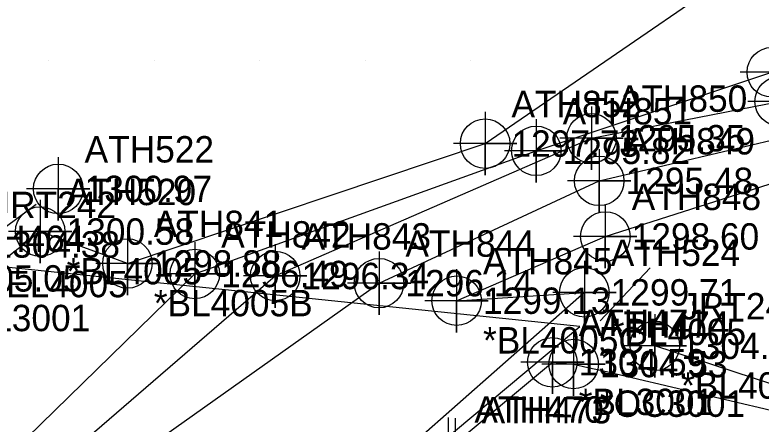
# Model space of a CAD drawing. Extents: x 1234484 to 1235382, y 695050 to 695510.
# Drawn here: x 1234936.8 to 1235007.5, y 695315.6 to 695354.3 of the extents above; entities that cross this region are included whole.
import ezdxf

# ---------------------------------------------------------------- set-up
doc = ezdxf.new("R2010")
doc.units = 0
for name, color, linetype in [('Exist DTM Breakline', 7, 'Continuous'), ('Exist DTM Breakline Cogo Comment', 7, 'Continuous'), ('Exist DTM Breakline Cogo Elevation', 7, 'Continuous'), ('Exist DTM Breakline Cogo Number', 7, 'Continuous'), ('Exist DTM Breakline Cogo Point CELL', 7, 'Continuous'), ('Exist DTM Breakline Underwater', 7, 'Continuous'), ('Exist DTM Crownline Cogo Number', 7, 'Continuous'), ('Exist DTM Crownline Cogo Point CELL', 7, 'Continuous'), ('Exist DTM Drainline Cogo Elevation', 7, 'Continuous'), ('Exist DTM Drainline Cogo Number', 7, 'Continuous'), ('Exist DTM Drainline Cogo Point CELL', 7, 'Continuous'), ('Exist DTM QL2 LIDAR Elevation Point', 7, 'Continuous'), ('Exist DTM Regular Point CELL', 7, 'Continuous'), ('Exist DTM Regular Point Cogo Elevation', 7, 'Continuous'), ('Exist DTM Regular Point Cogo Number', 7, 'Continuous'), ('Exist DTM Regular Point Underwater CELL', 7, 'Continuous'), ('Exist DTM Regular Point Underwater Cogo Elevation', 7, 'Continuous'), ('Exist DTM Regular Point Underwater Cogo Number', 7, 'Continuous'), ('Exist Hydro Stream or Body of Water', 7, 'Continuous'), ('Exist Roads EOP', 7, 'Continuous'), ('Exist Roads EOP Cogo Comment', 7, 'Continuous'), ('Exist Roads EOP Cogo Elevation', 7, 'Continuous'), ('Exist Roads EOP Cogo Number', 7, 'Continuous'), ('Exist Roads EOP Cogo Point CELL', 7, 'Continuous'), ('Exist Structure Major Deck Tunnel Box Culvert', 7, 'Continuous')]:
    doc.layers.add(name, color=color, linetype=linetype)

msp = doc.modelspace()

# ---------------------------------------------------------------- linework, layer by layer
at = {"layer": 'Exist DTM Breakline'}
for p, q in [((1234932.724, 695331.913), (1234938.803, 695336.41)), ((1234939.196, 695333.825), (1234905.457, 695307.608)), ((1234947.461, 695330.8), (1234939.196, 695333.825)), ((1234992.275, 695325.377), (1234997.012, 695330.381)), ((1234990.761, 695328.067), (1234961.429, 695302.218)), ((1234978.66, 695327.276), (1234990.761, 695328.067))]:
    msp.add_line(p, q, dxfattribs=at)
for points in [[(1234947.461, 695330.8), (1234981.356, 695342.155), (1235004.028, 695357.73), (1235022.786, 695369.361), (1235002.521, 695380.756), (1235001.421, 695384.893), (1235033.023, 695378.856), (1235065.819, 695386.67), (1235084.63, 695404.567)], [(1234978.66, 695327.276), (1234992.748, 695333.364), (1235012.047, 695339.528), (1235045.835, 695358.491), (1235079.523, 695374.606), (1235097.5, 695391.337)], [(1235319.256, 695177.55), (1235278.534, 695201.47), (1235237.781, 695224.217), (1235188.481, 695250.698), (1235134.96, 695275.849), (1235082.338, 695295.901), (1235034.938, 695310.723), (1234997.435, 695322.999)]]:
    msp.add_lwpolyline(points, dxfattribs=at)
at = {"layer": 'Exist DTM Breakline Cogo Point CELL'}
for points in [[(1234981.356, 695345.155), (1234981.356, 695339.155), (1234981.356, 695342.155), (1234984.356, 695342.155), (1234978.356, 695342.155)], [(1234939.196, 695336.825), (1234939.196, 695330.825), (1234939.196, 695333.825), (1234942.196, 695333.825), (1234936.196, 695333.825)], [(1234992.748, 695336.364), (1234992.748, 695330.364), (1234992.748, 695333.364), (1234995.748, 695333.364), (1234989.748, 695333.364)], [(1234947.461, 695333.8), (1234947.461, 695327.8), (1234947.461, 695330.8), (1234950.461, 695330.8), (1234944.461, 695330.8)], [(1234990.761, 695331.067), (1234990.761, 695325.067), (1234990.761, 695328.067), (1234993.761, 695328.067), (1234987.761, 695328.067)], [(1234978.66, 695330.276), (1234978.66, 695324.276), (1234978.66, 695327.276), (1234981.66, 695327.276), (1234975.66, 695327.276)], [(1234997.435, 695325.999), (1234997.435, 695319.999), (1234997.435, 695322.999), (1235000.435, 695322.999), (1234994.435, 695322.999)]]:
    msp.add_lwpolyline(points, dxfattribs=at)
for centre in [(1234981.356, 695342.155), (1234939.196, 695333.825), (1234992.748, 695333.364), (1234947.461, 695330.8), (1234990.761, 695328.067), (1234978.66, 695327.276), (1234997.435, 695322.999)]:
    msp.add_circle(centre, 2.344, dxfattribs=at)
at = {"layer": 'Exist DTM Breakline Underwater'}
msp.add_lwpolyline([(1234766.421, 695209.389), (1234812.885, 695247.237), (1234843.411, 695272.621), (1234869.986, 695279.055), (1234895.378, 695289.036), (1234916.238, 695295.408), (1234934.131, 695306.081), (1234961.466, 695329.617), (1234991.436, 695342.664), (1235009.265, 695346.147), (1235040.352, 695365.623), (1235072.367, 695380.008), (1235092.174, 695396.335)], dxfattribs=at)
at = {"layer": 'Exist DTM Crownline Cogo Point CELL'}
for points in [[(1234977.842, 695316.219), (1234977.842, 695310.219), (1234977.842, 695313.219), (1234980.842, 695313.219), (1234974.842, 695313.219)], [(1234978.534, 695316.159), (1234978.534, 695310.159), (1234978.534, 695313.159), (1234981.534, 695313.159), (1234975.534, 695313.159)]]:
    msp.add_lwpolyline(points, dxfattribs=at)
at = {"layer": 'Exist DTM Drainline Cogo Point CELL'}
for points in [[(1235008.526, 695351.915), (1235008.526, 695345.915), (1235008.526, 695348.915), (1235011.526, 695348.915), (1235005.526, 695348.915)], [(1234986.204, 695344.472), (1234986.204, 695338.472), (1234986.204, 695341.472), (1234989.204, 695341.472), (1234983.204, 695341.472)], [(1234992.169, 695341.626), (1234992.169, 695335.626), (1234992.169, 695338.626), (1234995.169, 695338.626), (1234989.169, 695338.626)], [(1234953.845, 695332.807), (1234953.845, 695326.807), (1234953.845, 695329.807), (1234956.845, 695329.807), (1234950.845, 695329.807)], [(1234971.304, 695331.94), (1234971.304, 695325.94), (1234971.304, 695328.94), (1234974.304, 695328.94), (1234968.304, 695328.94)]]:
    msp.add_lwpolyline(points, dxfattribs=at)
for centre in [(1235008.526, 695348.915), (1234986.204, 695341.472), (1234992.169, 695338.626), (1234953.845, 695329.807), (1234971.304, 695328.94)]:
    msp.add_circle(centre, 2.344, dxfattribs=at)
at = {"layer": 'Exist DTM QL2 LIDAR Elevation Point'}
for p, q in [((1234940, 695350), (1234940, 695350)), ((1234950, 695350), (1234950, 695350)), ((1234960, 695350), (1234960, 695350)), ((1234970, 695350), (1234970, 695350)), ((1234980, 695350), (1234980, 695350)), ((1234940, 695340), (1234940, 695340))]:
    msp.add_line(p, q, dxfattribs=at)
at = {"layer": 'Exist DTM Regular Point CELL'}
msp.add_lwpolyline([(1234940.904, 695340.865), (1234940.904, 695334.865), (1234940.904, 695337.865), (1234943.904, 695337.865), (1234937.904, 695337.865)], dxfattribs=at)
msp.add_circle((1234940.904, 695337.865), 2.344, dxfattribs=at)
at = {"layer": 'Exist DTM Regular Point Underwater CELL'}
for points in [[(1235009.265, 695349.147), (1235009.265, 695343.147), (1235009.265, 695346.147), (1235012.265, 695346.147), (1235006.265, 695346.147)], [(1234991.436, 695345.664), (1234991.436, 695339.664), (1234991.436, 695342.664), (1234994.436, 695342.664), (1234988.436, 695342.664)], [(1234961.466, 695332.617), (1234961.466, 695326.617), (1234961.466, 695329.617), (1234964.466, 695329.617), (1234958.466, 695329.617)]]:
    msp.add_lwpolyline(points, dxfattribs=at)
for centre in [(1235009.265, 695346.147), (1234991.436, 695342.664), (1234961.466, 695329.617)]:
    msp.add_circle(centre, 2.344, dxfattribs=at)
at = {"layer": 'Exist Hydro Stream or Body of Water'}
for points in [[(1234766.439, 695214.543), (1234809.451, 695250.146), (1234840.783, 695273.683), (1234870.231, 695281.467), (1234894.384, 695292.767), (1234915.014, 695298.345), (1234929.933, 695306.511), (1234953.845, 695329.807), (1234986.204, 695341.472), (1235008.526, 695348.915), (1235037.336, 695368.653), (1235069.491, 695383.302), (1235088.448, 695400.861)], [(1234938.044, 695305.366), (1234971.304, 695328.94), (1234992.169, 695338.626), (1235010.649, 695342.979), (1235043.523, 695362.073), (1235076.562, 695377.561), (1235094.01, 695394.044)]]:
    msp.add_lwpolyline(points, dxfattribs=at)
at = {"layer": 'Exist Roads EOP'}
msp.add_line((1234987.73, 695321.443), (1234989.744, 695321.275), dxfattribs=at)
msp.add_lwpolyline([(1234968.075, 695304.88), (1234977.842, 695313.219), (1234987.73, 695321.443)], dxfattribs=at)
msp.add_spline([(1234989.744, 695321.275), (1235032.632, 695310.758), (1235082.97, 695294.625), (1235134.247, 695274.482), (1235183.928, 695250.955), (1235232.115, 695225.68)], degree=3, dxfattribs=at)
at = {"layer": 'Exist Roads EOP Cogo Point CELL'}
for points in [[(1234987.73, 695324.443), (1234987.73, 695318.443), (1234987.73, 695321.443), (1234990.73, 695321.443), (1234984.73, 695321.443)], [(1234989.744, 695324.275), (1234989.744, 695318.275), (1234989.744, 695321.275), (1234992.744, 695321.275), (1234986.744, 695321.275)]]:
    msp.add_lwpolyline(points, dxfattribs=at)
for centre in [(1234987.73, 695321.443), (1234989.744, 695321.275)]:
    msp.add_circle(centre, 2.344, dxfattribs=at)
at = {"layer": 'Exist Structure Major Deck Tunnel Box Culvert'}
msp.add_lwpolyline([(1234932.242, 695330.836), (1234906.381, 695309.848), (1234965.045, 695303.686), (1234990.33, 695324.837), (1234932.242, 695330.836)], dxfattribs=at)

# ---------------------------------------------------------------- texts
at = {"layer": 'Exist DTM Breakline Cogo Comment'}
for s, p in [('*BL4005', (1234941.696, 695328.825)), ('*EL4005', (1234934.671, 695327.602)), ('*BL4005B', (1234949.961, 695325.8)), ('*BL4005', (1234993.261, 695323.067)), ('*BL4005C', (1234981.16, 695322.276)), ('*BL4005', (1234999.935, 695317.999))]:
    msp.add_text(s, height=2.5, dxfattribs=at).set_placement(p)
at = {"layer": 'Exist DTM Breakline Cogo Elevation'}
for s, p in [('1297.73', (1234983.856, 695340.905)), ('1300.58', (1234941.696, 695332.575)), ('1298.60', (1234995.248, 695332.114)), ('1304.38', (1234934.671, 695331.352)), ('1298.88', (1234949.961, 695329.55)), ('1299.71', (1234993.261, 695326.817)), ('1299.13', (1234981.16, 695326.026)), ('1304.20', (1234999.935, 695321.749))]:
    msp.add_text(s, height=2.5, dxfattribs=at).set_placement(p)
at = {"layer": 'Exist DTM Breakline Cogo Number'}
for s, p in [('ATH852', (1234983.856, 695344.655)), ('ATH520', (1234941.696, 695336.325)), ('ATH848', (1234995.248, 695335.864)), ('JRT242', (1234934.671, 695335.102)), ('ATH841', (1234949.961, 695333.3)), ('ATH524', (1234993.261, 695330.567)), ('ATH845', (1234981.16, 695329.776)), ('JRT243', (1234999.935, 695325.499))]:
    msp.add_text(s, height=2.5, dxfattribs=at).set_placement(p)
at = {"layer": 'Exist DTM Crownline Cogo Number'}
for s, p in [('ATH470', (1234980.342, 695315.719)), ('ATH473', (1234981.034, 695315.659))]:
    msp.add_text(s, height=2.5, dxfattribs=at).set_placement(p)
at = {"layer": 'Exist DTM Drainline Cogo Elevation'}
for s, p in [('1295.82', (1234988.704, 695340.222)), ('1295.48', (1234994.669, 695337.376)), ('1296.49', (1234956.345, 695328.557)), ('1296.14', (1234973.804, 695327.69))]:
    msp.add_text(s, height=2.5, dxfattribs=at).set_placement(p)
at = {"layer": 'Exist DTM Drainline Cogo Number'}
for s, p in [('ATH851', (1234988.704, 695343.972)), ('ATH849', (1234994.669, 695341.126)), ('ATH842', (1234956.345, 695332.307)), ('ATH844', (1234973.804, 695331.44))]:
    msp.add_text(s, height=2.5, dxfattribs=at).set_placement(p)
at = {"layer": 'Exist DTM Regular Point Cogo Elevation'}
msp.add_text('1300.97', height=2.5, dxfattribs=at).set_placement((1234943.404, 695336.615))
at = {"layer": 'Exist DTM Regular Point Cogo Number'}
msp.add_text('ATH522', height=2.5, dxfattribs=at).set_placement((1234943.404, 695340.365))
at = {"layer": 'Exist DTM Regular Point Underwater Cogo Elevation'}
for s, p in [('1295.35', (1234993.936, 695341.414)), ('1296.34', (1234963.966, 695328.367))]:
    msp.add_text(s, height=2.5, dxfattribs=at).set_placement(p)
at = {"layer": 'Exist DTM Regular Point Underwater Cogo Number'}
for s, p in [('ATH850', (1234993.936, 695345.164)), ('ATH843', (1234963.966, 695332.117))]:
    msp.add_text(s, height=2.5, dxfattribs=at).set_placement(p)
at = {"layer": 'Exist Roads EOP Cogo Comment'}
for s, p in [('*EL3001', (1234931.113, 695324.389)), ('*BL3001', (1234990.23, 695316.443)), ('*OC3001', (1234992.244, 695316.275))]:
    msp.add_text(s, height=2.5, dxfattribs=at).set_placement(p)
at = {"layer": 'Exist Roads EOP Cogo Elevation'}
for s, p in [('1305.05', (1234931.113, 695328.139)), ('1304.59', (1234990.23, 695320.193)), ('1304.53', (1234992.244, 695320.025))]:
    msp.add_text(s, height=2.5, dxfattribs=at).set_placement(p)
at = {"layer": 'Exist Roads EOP Cogo Number'}
for s, p in [('ATH464', (1234931.113, 695331.889)), ('ATH471', (1234990.23, 695323.943)), ('ATH474', (1234992.244, 695323.775))]:
    msp.add_text(s, height=2.5, dxfattribs=at).set_placement(p)

doc.saveas('drawing.dxf')
